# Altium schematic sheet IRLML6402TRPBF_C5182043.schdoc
size 127 x 101 mm
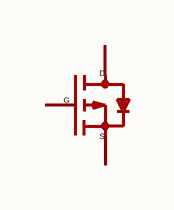
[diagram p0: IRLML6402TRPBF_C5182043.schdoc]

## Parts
Q?  irlml6402trpbf_c5182043  [SOT-23-3_L2.9-W1.3-P1.90-LS2.4-BR]  (value not drawn)

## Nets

Not connected (* = marked no-connect by the designer): Q? 1(G) 2(S) 3(D)

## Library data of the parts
Q? = irlml6402trpbf_c5182043: 数量:1个P沟道;漏源电压(Vdss):20V;连续漏极电流(Id):4.1A;导通电阻(RDS(on)):75mΩ@2.5V;耗散功率(Pd):1.7W;阈值电压(Vgs(th)):1V;; Manufacturer: TECH PUBLIC(台舟); AddInBom: yes; ModelId: c62791f0466c4ae2a892c056b845b0ca; ModelName: SOT-23-3P_L2.9-W1.3-H1.0-LS2.4-P0.95; ModelTransform: 98.425,114.173,0,180,0,0,0.0005,-0.0005,0; Number: 1个P沟道; Drain to Source Voltage: 20V; Current - Continuous Drain(Id): 4.1A; Pd - Power Dissipation: 1.7W; Gate Threshold Voltage (Vgs(th)): 1V; Gate Charge(Qg): 7.8nC@4.5V; Input Capacitance(Ciss): 740pF; Reverse Transfer Capacitance (Crss@Vds): 190pF; Type: P沟道; Output Capacitance(Coss): 290pF; Vgs: ±12V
